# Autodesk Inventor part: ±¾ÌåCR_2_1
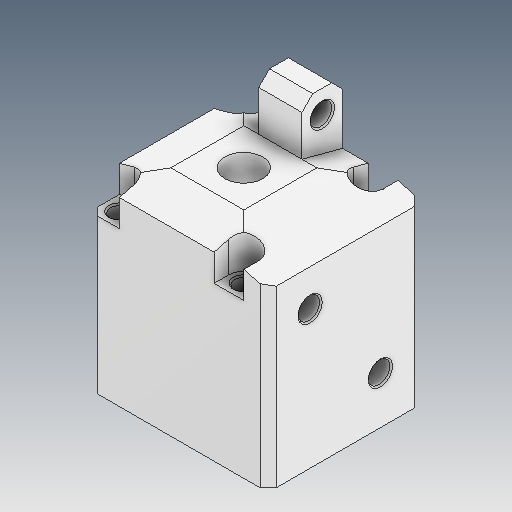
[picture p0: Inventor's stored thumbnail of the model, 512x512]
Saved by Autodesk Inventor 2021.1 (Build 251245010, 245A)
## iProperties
Created: 2021-05
Part Number: ±¾ÌåCR_2_1
Material: Ogólny
Document SubType Name: Modeling
Designer: user
Density: 1 g/cm^3
Appearance: Domyślna
Author: user
Revision Number: ÈÎºÎ
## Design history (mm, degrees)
feature "ÊäÈë1"
node "Bryła1"
